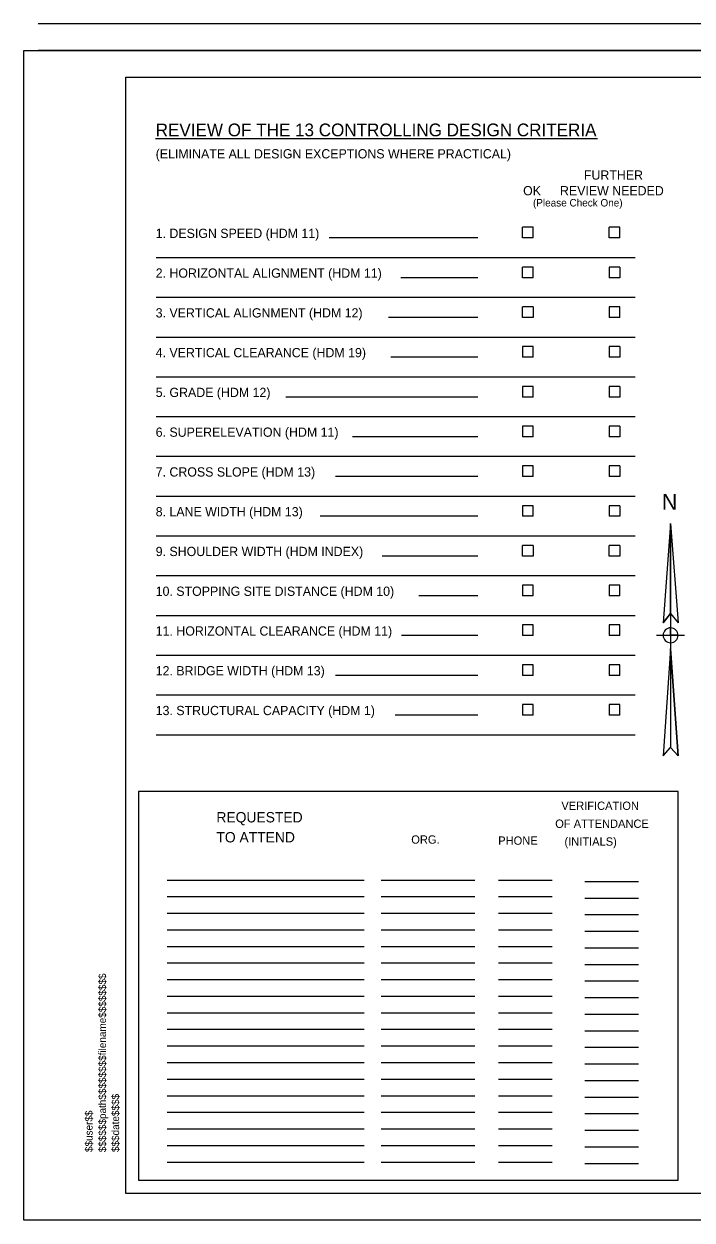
# Model space of a CAD drawing. Extents: x 8134 to 11793, y 3225 to 13425.
# Drawn here: x 9986 to 10615, y 11150 to 12275 of the extents above; entities that cross this region are included whole.
import ezdxf

# ---------------------------------------------------------------- set-up
doc = ezdxf.new("R2010")
doc.units = 0
for name, color, linetype in [('RD_EX_Misc', 7, 'Continuous'), ('RD_SHT_Bndy', 7, 'Continuous'), ('RD_SHT_ID', 7, 'Continuous'), ('RD_SHT_IplotShp', 7, 'Continuous'), ('RD_SHT_TX', 7, 'Continuous')]:
    doc.layers.add(name, color=color, linetype=linetype)

msp = doc.modelspace()

# ---------------------------------------------------------------- linework, layer by layer
at = {"layer": 'RD_EX_Misc'}
for p, q in [((10594.7, 11805.1), (10587.8, 11711.8)), ((10594.7, 11805.1), (10602, 11711.8)), ((10594.7, 11805.1), (10594.7, 11594.4)), ((10594.7, 11720.4), (10587.8, 11711.8)), ((10594.7, 11720.4), (10602, 11711.8)), ((10581.5, 11700), (10607.9, 11700)), ((10594.7, 11687.4), (10587.8, 11586.6)), ((10594.7, 11687.4), (10601.8, 11586.6)), ((10587.8, 11586.6), (10594.8, 11594.6)), ((10601.8, 11586.6), (10594.8, 11594.6))]:
    msp.add_line(p, q, dxfattribs=at)
for points in [[(10594.7, 11720.4), (10594.7, 11805.1), (10587.8, 11711.8), (10594.7, 11720.4)], [(10587.7, 11700), (10594.7, 11700)], [(10594.7, 11700), (10594.7, 11707)], [(10594.7, 11700), (10594.7, 11693)], [(10601.7, 11700), (10594.7, 11700)], [(10594.7, 11687.4), (10594.7, 11594.6), (10594.8, 11594.6), (10601.8, 11586.6), (10594.7, 11687.4)]]:
    msp.add_lwpolyline(points, dxfattribs=at)
for start, end in [(89.5907, 180), (89.5907, 180), (180, 270.4093), (0, 89.5907), (270.4093, 0), (270.4093, 0)]:
    msp.add_arc((10594.7, 11700), 7, start, end, dxfattribs=at)
at = {"layer": 'RD_SHT_Bndy'}
for p, q in [((11760, 12275), (10000, 12275)), ((11760, 12275), (10000, 12275)), ((11760, 12250), (10000, 12250)), ((10525.9, 12166.8), (10110.2, 12166.8)), ((10465.5, 12083.7), (10455.5, 12083.7)), ((10455.5, 12073.7), (10455.5, 12083.7)), ((10465.5, 12073.7), (10465.5, 12083.7)), ((10547, 12083.7), (10537, 12083.7)), ((10537, 12073.7), (10537, 12083.7)), ((10547, 12073.7), (10547, 12083.7)), ((10413.3, 12073.7), (10273.7, 12073.7)), ((10465.5, 12073.7), (10455.5, 12073.7)), ((10547, 12073.7), (10537, 12073.7)), ((10561.4, 12055), (10110.7, 12055)), ((10465.5, 12046.3), (10455.5, 12046.3)), ((10455.5, 12036.3), (10455.5, 12046.3)), ((10465.5, 12036.3), (10465.5, 12046.3)), ((10547, 12046.3), (10537, 12046.3)), ((10537, 12046.3), (10537, 12036.3)), ((10547, 12046.3), (10547, 12036.3)), ((10413.3, 12036.3), (10340.9, 12036.3)), ((10465.5, 12036.3), (10455.5, 12036.3)), ((10547, 12036.3), (10537, 12036.3)), ((10561.4, 12017.6), (10110.7, 12017.6)), ((10465.5, 12008.9), (10455.5, 12008.9)), ((10455.5, 11998.9), (10455.5, 12008.9)), ((10465.5, 12008.9), (10465.5, 11998.9)), ((10547, 12008.9), (10537, 12008.9)), ((10537, 12008.9), (10537, 11998.9)), ((10547, 11998.9), (10547, 12008.9)), ((10413.3, 11998.9), (10329.3, 11998.9)), ((10465.5, 11998.9), (10455.5, 11998.9)), ((10547, 11998.9), (10537, 11998.9)), ((10561.4, 11980.2), (10110.7, 11980.2)), ((10465.5, 11971.5), (10455.5, 11971.5)), ((10455.5, 11971.5), (10455.5, 11961.5)), ((10465.5, 11961.5), (10465.5, 11971.5)), ((10547, 11971.5), (10537, 11971.5)), ((10537, 11971.5), (10537, 11961.5)), ((10547, 11971.5), (10547, 11961.5)), ((10413.3, 11961.5), (10331.7, 11961.5)), ((10465.5, 11961.5), (10455.5, 11961.5)), ((10547, 11961.5), (10537, 11961.5)), ((10561.4, 11942.8), (10110.7, 11942.8)), ((10465.5, 11934.1), (10455.5, 11934.1)), ((10455.5, 11934.1), (10455.5, 11924.1)), ((10465.5, 11924.1), (10465.5, 11934.1)), ((10547, 11934.1), (10537, 11934.1)), ((10537, 11934.1), (10537, 11924.1)), ((10547, 11934.1), (10547, 11924.1)), ((10413.3, 11924.1), (10232.7, 11924.1)), ((10465.5, 11924.1), (10455.5, 11924.1)), ((10547, 11924.1), (10537, 11924.1)), ((10561.4, 11905.4), (10110.7, 11905.4)), ((10465.5, 11896.7), (10455.5, 11896.7)), ((10455.5, 11896.7), (10455.5, 11886.7)), ((10465.5, 11886.7), (10465.5, 11896.7)), ((10547, 11896.7), (10537, 11896.7)), ((10537, 11896.7), (10537, 11886.7)), ((10547, 11896.7), (10547, 11886.7)), ((10413.3, 11886.7), (10295.4, 11886.7)), ((10465.5, 11886.7), (10455.5, 11886.7)), ((10547, 11886.7), (10537, 11886.7)), ((10561.4, 11868), (10110.7, 11868)), ((10465.5, 11859.3), (10455.5, 11859.3)), ((10455.5, 11859.3), (10455.5, 11849.3)), ((10465.5, 11849.3), (10465.5, 11859.3)), ((10547, 11859.3), (10537, 11859.3)), ((10537, 11859.3), (10537, 11849.3)), ((10547, 11859.3), (10547, 11849.3)), ((10413.3, 11849.3), (10279.6, 11849.3)), ((10465.5, 11849.3), (10455.5, 11849.3)), ((10547, 11849.3), (10537, 11849.3)), ((10561.4, 11830.6), (10110.7, 11830.6)), ((10465.5, 11821.9), (10455.5, 11821.9)), ((10455.5, 11821.9), (10455.5, 11811.9)), ((10465.5, 11811.9), (10465.5, 11821.9)), ((10547, 11821.9), (10537, 11821.9)), ((10537, 11821.9), (10537, 11811.9)), ((10547, 11821.9), (10547, 11811.9)), ((10413.3, 11811.9), (10265.2, 11811.9)), ((10465.5, 11811.9), (10455.5, 11811.9)), ((10547, 11811.9), (10537, 11811.9)), ((10561.4, 11793.2), (10110.7, 11793.2)), ((10465.5, 11784.5), (10455.5, 11784.5)), ((10455.5, 11774.5), (10455.5, 11784.5)), ((10465.5, 11784.5), (10465.5, 11774.5)), ((10547, 11784.5), (10537, 11784.5)), ((10537, 11774.5), (10537, 11784.5)), ((10547, 11784.5), (10547, 11774.5)), ((10413.3, 11774.5), (10323.5, 11774.5)), ((10465.5, 11774.5), (10455.5, 11774.5)), ((10547, 11774.5), (10537, 11774.5)), ((10561.4, 11755.8), (10110.7, 11755.8)), ((10465.5, 11747.1), (10455.5, 11747.1)), ((10455.5, 11747.1), (10455.5, 11737.1)), ((10465.5, 11737.1), (10465.5, 11747.1)), ((10547, 11747.1), (10537, 11747.1)), ((10537, 11747.1), (10537, 11737.1)), ((10547, 11737.1), (10547, 11747.1)), ((10413.3, 11737.1), (10358, 11737.1)), ((10465.5, 11737.1), (10455.5, 11737.1)), ((10547, 11737.1), (10537, 11737.1)), ((10561.4, 11718.4), (10110.7, 11718.4)), ((10465.5, 11709.7), (10455.5, 11709.7)), ((10455.5, 11709.7), (10455.5, 11699.7)), ((10465.5, 11699.7), (10465.5, 11709.7)), ((10547, 11709.7), (10537, 11709.7)), ((10537, 11709.7), (10537, 11699.7)), ((10547, 11699.7), (10547, 11709.7)), ((10413.3, 11699.7), (10341.5, 11699.7)), ((10465.5, 11699.7), (10455.5, 11699.7)), ((10547, 11699.7), (10537, 11699.7)), ((10561.4, 11681), (10110.7, 11681)), ((10465.5, 11672.3), (10455.5, 11672.3)), ((10455.5, 11672.3), (10455.5, 11662.3)), ((10465.5, 11662.3), (10465.5, 11672.3)), ((10547, 11672.3), (10537, 11672.3)), ((10537, 11672.3), (10537, 11662.3)), ((10547, 11662.3), (10547, 11672.3)), ((10413.3, 11662.3), (10279.6, 11662.3)), ((10465.5, 11662.3), (10455.5, 11662.3)), ((10547, 11662.3), (10537, 11662.3)), ((10561.4, 11643.6), (10110.7, 11643.6)), ((10465.5, 11634.9), (10455.5, 11634.9)), ((10455.5, 11634.9), (10455.5, 11624.9)), ((10465.5, 11624.9), (10465.5, 11634.9)), ((10547, 11634.9), (10537, 11634.9)), ((10537, 11634.9), (10537, 11624.9)), ((10547, 11624.9), (10547, 11634.9)), ((10413.3, 11624.9), (10335.7, 11624.9)), ((10465.5, 11624.9), (10455.5, 11624.9)), ((10547, 11624.9), (10537, 11624.9)), ((10561.4, 11606.2), (10110.7, 11606.2)), ((10121.3, 11469.8), (10306.4, 11469.8)), ((10322.4, 11469.8), (10410.6, 11469.8)), ((10432.8, 11469.8), (10483.2, 11469.8)), ((10514.1, 11468.5), (10564.4, 11468.5)), ((10121.3, 11454.2), (10306.4, 11454.2)), ((10322.4, 11454.2), (10410.6, 11454.2)), ((10432.8, 11454.2), (10483.2, 11454.2)), ((10514.1, 11452.9), (10564.4, 11452.9)), ((10121.3, 11438.6), (10306.4, 11438.6)), ((10322.4, 11438.6), (10410.6, 11438.6)), ((10432.8, 11438.6), (10483.2, 11438.6)), ((10514.1, 11437.3), (10564.4, 11437.3)), ((10121.3, 11423), (10306.4, 11423)), ((10322.4, 11423), (10410.6, 11423)), ((10432.8, 11423), (10483.2, 11423)), ((10514.1, 11421.7), (10564.4, 11421.7)), ((10121.3, 11407.4), (10306.4, 11407.4)), ((10322.4, 11407.4), (10410.6, 11407.4)), ((10432.8, 11407.4), (10483.2, 11407.4)), ((10514.1, 11406.1), (10564.4, 11406.1)), ((10121.3, 11391.8), (10306.4, 11391.8)), ((10322.4, 11391.8), (10410.6, 11391.8)), ((10432.8, 11391.8), (10483.2, 11391.8)), ((10514.1, 11390.5), (10564.4, 11390.5)), ((10121.3, 11376.2), (10306.4, 11376.2)), ((10322.4, 11376.2), (10410.6, 11376.2)), ((10432.8, 11376.2), (10483.2, 11376.2)), ((10514.1, 11374.9), (10564.4, 11374.9)), ((10121.3, 11360.6), (10306.4, 11360.6)), ((10322.4, 11360.6), (10410.6, 11360.6)), ((10432.8, 11360.6), (10483.2, 11360.6)), ((10514.1, 11359.3), (10564.4, 11359.3)), ((10121.3, 11345), (10306.4, 11345)), ((10322.4, 11345), (10410.6, 11345)), ((10432.8, 11345), (10483.2, 11345)), ((10514.1, 11343.7), (10564.4, 11343.7)), ((10121.3, 11329.4), (10306.4, 11329.4)), ((10322.4, 11329.4), (10410.6, 11329.4)), ((10432.8, 11329.4), (10483.2, 11329.4)), ((10514.1, 11328.1), (10564.4, 11328.1)), ((10121.3, 11313.8), (10306.4, 11313.8)), ((10322.4, 11313.8), (10410.6, 11313.8)), ((10432.8, 11313.8), (10483.2, 11313.8)), ((10514.1, 11312.5), (10564.4, 11312.5)), ((10121.3, 11298.2), (10306.4, 11298.2)), ((10322.4, 11298.2), (10410.6, 11298.2)), ((10432.8, 11298.2), (10483.2, 11298.2)), ((10514.1, 11296.9), (10564.4, 11296.9)), ((10121.3, 11282.6), (10306.4, 11282.6)), ((10322.4, 11282.6), (10410.6, 11282.6)), ((10432.8, 11282.6), (10483.2, 11282.6)), ((10514.1, 11281.3), (10564.4, 11281.3)), ((10121.3, 11267), (10306.4, 11267)), ((10322.4, 11267), (10410.6, 11267)), ((10432.8, 11267), (10483.2, 11267)), ((10514.1, 11265.7), (10564.4, 11265.7)), ((10121.3, 11251.4), (10306.4, 11251.4)), ((10322.4, 11251.4), (10410.6, 11251.4)), ((10432.8, 11251.4), (10483.2, 11251.4)), ((10514.1, 11250.1), (10564.4, 11250.1)), ((10121.3, 11235.8), (10306.4, 11235.8)), ((10322.4, 11235.8), (10410.6, 11235.8)), ((10432.8, 11235.8), (10483.2, 11235.8)), ((10514.1, 11234.5), (10564.4, 11234.5)), ((10121.3, 11220.2), (10306.4, 11220.2)), ((10322.4, 11220.2), (10410.6, 11220.2)), ((10432.8, 11220.2), (10483.2, 11220.2)), ((10514.1, 11218.9), (10564.4, 11218.9)), ((10121.3, 11204.6), (10306.4, 11204.6)), ((10322.4, 11204.6), (10410.6, 11204.6)), ((10432.8, 11204.6), (10483.2, 11204.6)), ((10514.1, 11203.3), (10564.4, 11203.3)), ((11760, 11150), (10000, 11150))]:
    msp.add_line(p, q, dxfattribs=at)
for points in [[(10082.4, 12225), (11757.4, 12225), (11757.4, 11175), (10082.4, 11175)], [(10094.2, 11553), (10094.2, 11187.6), (10601.7, 11187.6), (10601.7, 11553)]]:
    msp.add_lwpolyline(points, close=True, dxfattribs=at)
at = {"layer": 'RD_SHT_IplotShp'}
msp.add_lwpolyline([(9986.4, 12250), (11782.4, 12250), (11782.4, 11150), (9986.4, 11150)], close=True, dxfattribs=at)

# ---------------------------------------------------------------- texts
at = {"layer": 'RD_EX_Misc'}
msp.add_text('N', height=15, dxfattribs=at).set_placement((10586.6, 11818))
at = {"layer": 'RD_SHT_ID'}
for s, p in [('$$$$$$path$$$$$$$$filename$$$$$$$$', (10063.7, 11213.8)), ('$$$date$$$$', (10076, 11214)), ('$$user$$', (10051, 11214))]:
    msp.add_text(s, height=7, rotation=90, dxfattribs=at).set_placement(p)
at = {"layer": 'RD_SHT_TX'}
for s, height, p in [('REVIEW OF THE 13 CONTROLLING DESIGN CRITERIA', 12, (10110.4, 12169.3)), ('(ELIMINATE ALL DESIGN EXCEPTIONS WHERE PRACTICAL)', 8.7, (10110.4, 12148.5)), ('FURTHER', 8.7, (10513.2, 12128.5)), ('OK', 8.7, (10456, 12113.8)), ('REVIEW NEEDED', 8.7, (10490.7, 12113.8)), ('(Please Check One)', 7, (10465.3, 12103.3)), ('1. DESIGN SPEED (HDM 11)', 8.7, (10110.4, 12073.7)), ('2. HORIZONTAL ALIGNMENT (HDM 11)', 8.7, (10110.4, 12036.3)), ('3. VERTICAL ALIGNMENT (HDM 12)', 8.7, (10110.4, 11998.9)), ('4. VERTICAL CLEARANCE (HDM 19)', 8.7, (10110.4, 11961.5)), ('5. GRADE (HDM 12)', 8.7, (10110.4, 11924.1)), ('6. SUPERELEVATION (HDM 11)', 8.7, (10110.4, 11886.7)), ('7. CROSS SLOPE (HDM 13)', 8.7, (10110.4, 11849.3)), ('8. LANE WIDTH (HDM 13)', 8.7, (10110.4, 11811.9)), ('9. SHOULDER WIDTH (HDM INDEX)', 8.7, (10110.4, 11774.5)), ('10. STOPPING SITE DISTANCE (HDM 10)', 8.7, (10110.4, 11737.1)), ('11. HORIZONTAL CLEARANCE (HDM 11)', 8.7, (10110.4, 11699.7)), ('12. BRIDGE WIDTH (HDM 13)', 8.7, (10110.4, 11662.3)), ('13. STRUCTURAL CAPACITY (HDM 1)', 8.7, (10110.4, 11624.9)), ('  VERIFICATION ', 7.8, (10486.2, 11535.8)), ('REQUESTED ', 9.75, (10167.5, 11524)), ('OF ATTENDANCE', 7.8, (10486.2, 11518.9)), ('TO ATTEND', 9.75, (10167.5, 11505.2)), ('ORG.', 7.8, (10350.8, 11504)), ('PHONE', 7.8, (10432.6, 11503)), ('   (INITIALS)', 7.8, (10486.2, 11502.1))]:
    msp.add_text(s, height=height, dxfattribs=at).set_placement(p)

doc.saveas('drawing.dxf')
